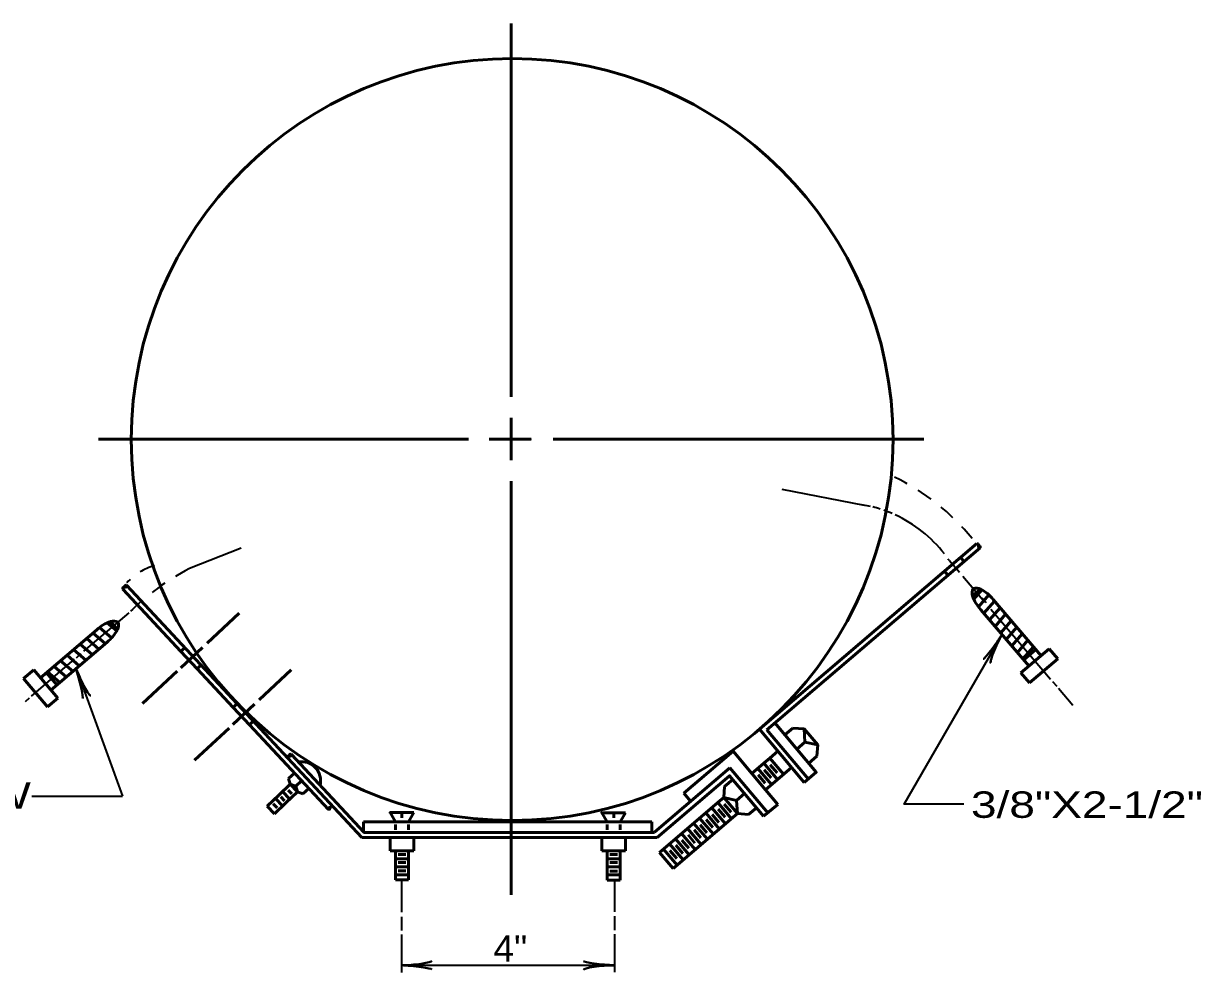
# Model space of a CAD drawing. Extents: x 12366 to 13046, y 9129 to 9570.
# Drawn here: x 12526.1 to 12636.6, y 9238.1 to 9327.8 of the extents above; entities that cross this region are included whole.
import ezdxf

# ---------------------------------------------------------------- set-up
doc = ezdxf.new("R2010")
doc.units = 0
doc.linetypes.add('SHORT_DASHED', pattern=[2.7, 1.5, -1.2])
doc.layers.add('1', color=7, linetype='Continuous', lineweight=53)

msp = doc.modelspace()

# ---------------------------------------------------------------- linework, layer by layer
at = {"layer": '1'}
for p, q in [((12572.209, 9292.546), (12572.209, 9327.828)), ((12572.209, 9288.528), (12572.209, 9290.556)), ((12533.209, 9288.528), (12568.171, 9288.528)), ((12570.139, 9288.528), (12574.118, 9288.528)), ((12572.209, 9286.552), (12572.209, 9288.528)), ((12576.18, 9288.528), (12611.209, 9288.528)), ((12595.683, 9261.128), (12616.214, 9278.663)), ((12596.384, 9261.069), (12616.539, 9278.282)), ((12614.693, 9277.364), (12615.018, 9276.984)), ((12613.172, 9276.065), (12613.497, 9275.685)), ((12558.088, 9250.881), (12535.852, 9274.727)), ((12540.994, 9268.479), (12535.495, 9274.376)), ((12615.827, 9273.727), (12616.583, 9274.372)), ((12615.943, 9273.411), (12616.716, 9274.3)), ((12616.375, 9272.689), (12617.361, 9273.824)), ((12616.611, 9272.423), (12621.156, 9267.102)), ((12616.905, 9272.079), (12617.9, 9273.224)), ((12617.431, 9271.464), (12618.426, 9272.609)), ((12617.76, 9273.388), (12622.296, 9268.077)), ((12534.352, 9271.297), (12534.998, 9270.541)), ((12543.474, 9269.252), (12546.516, 9272.088)), ((12617.956, 9270.849), (12618.951, 9271.994)), ((12618.481, 9270.234), (12619.476, 9271.379)), ((12533.049, 9270.513), (12527.728, 9265.968)), ((12532.705, 9270.219), (12533.85, 9269.224)), ((12533.314, 9270.749), (12534.449, 9269.763)), ((12534.037, 9271.181), (12534.926, 9270.409)), ((12619.006, 9269.619), (12620.002, 9270.764)), ((12534.014, 9269.364), (12528.703, 9264.828)), ((12531.475, 9269.168), (12532.62, 9268.173)), ((12532.09, 9269.694), (12533.235, 9268.699)), ((12619.532, 9269.004), (12620.527, 9270.148)), ((12620.057, 9268.389), (12621.052, 9269.533)), ((12530.245, 9268.118), (12531.389, 9267.123)), ((12530.86, 9268.643), (12532.004, 9267.648)), ((12541.351, 9268.829), (12540.994, 9268.479)), ((12542.529, 9266.833), (12540.994, 9268.479)), ((12540.997, 9266.943), (12543.045, 9268.853)), ((12623.057, 9268.726), (12620.395, 9266.453)), ((12620.583, 9267.774), (12621.578, 9268.918)), ((12621.809, 9268.647), (12620.669, 9267.673)), ((12623.057, 9268.726), (12623.869, 9267.776)), ((12529.015, 9267.067), (12530.159, 9266.072)), ((12529.63, 9267.592), (12530.774, 9266.597)), ((12542.886, 9267.183), (12542.529, 9266.833)), ((12623.869, 9267.776), (12621.207, 9265.503)), ((12527.079, 9266.729), (12526.128, 9265.917)), ((12528.401, 9263.256), (12526.128, 9265.917)), ((12529.352, 9264.067), (12527.079, 9266.729)), ((12529.273, 9265.315), (12528.299, 9266.456)), ((12528.399, 9266.542), (12529.544, 9265.547)), ((12537.373, 9263.564), (12540.633, 9266.604)), ((12545.94, 9263.175), (12542.529, 9266.833)), ((12548.383, 9263.888), (12551.425, 9266.725)), ((12620.395, 9266.453), (12621.207, 9265.503)), ((12529.352, 9264.067), (12528.401, 9263.256)), ((12545.906, 9261.579), (12547.955, 9263.489)), ((12546.297, 9263.525), (12545.94, 9263.175)), ((12547.475, 9261.529), (12545.94, 9263.175)), ((12547.832, 9261.879), (12547.475, 9261.529)), ((12554.932, 9253.533), (12547.475, 9261.529)), ((12542.283, 9258.201), (12545.543, 9261.24)), ((12595.683, 9261.128), (12599.898, 9256.104)), ((12596.384, 9261.069), (12600.281, 9256.426)), ((12598.074, 9260.587), (12598.835, 9261.237)), ((12599.899, 9261.159), (12601.198, 9259.638)), ((12599.222, 9259.244), (12599.971, 9259.906)), ((12551.985, 9258.159), (12551.419, 9258.765)), ((12551.422, 9258.762), (12551.422, 9258.762)), ((12558.276, 9251.413), (12551.454, 9258.728)), ((12588.548, 9255.068), (12593.194, 9259.037)), ((12596.097, 9257.912), (12596.667, 9258.399)), ((12596.667, 9258.399), (12597.427, 9259.049)), ((12596.667, 9258.399), (12597.952, 9256.867)), ((12600.347, 9257.926), (12601.108, 9258.575)), ((12551.723, 9256.986), (12551.17, 9256.479)), ((12585.776, 9251.386), (12592.894, 9257.465)), ((12592.894, 9257.465), (12596.458, 9253.217)), ((12594.956, 9256.938), (12596.096, 9257.912)), ((12595.526, 9257.425), (12596.812, 9255.893)), ((12596.096, 9257.912), (12597.382, 9256.38)), ((12596.136, 9257.288), (12596.786, 9256.528)), ((12596.242, 9255.406), (12598.713, 9257.516)), ((12596.707, 9257.775), (12597.356, 9257.015)), ((12551.326, 9255.92), (12550.238, 9254.887)), ((12551.326, 9255.92), (12552.014, 9255.195)), ((12552.399, 9256.249), (12551.846, 9255.742)), ((12593.15, 9256.381), (12592.378, 9255.722)), ((12595.566, 9256.801), (12596.215, 9256.041)), ((12550.238, 9254.888), (12549.15, 9253.855)), ((12550.785, 9254.359), (12550.441, 9254.722)), ((12551.295, 9254.512), (12550.606, 9255.237)), ((12551.474, 9255.02), (12551.142, 9255.369)), ((12553.074, 9255.512), (12552.521, 9255.005)), ((12588.548, 9255.068), (12589.191, 9254.302)), ((12594.275, 9255.041), (12593.514, 9254.391)), ((12596.242, 9255.406), (12597.408, 9254.015)), ((12549.838, 9253.13), (12549.15, 9253.855)), ((12550.081, 9253.698), (12549.724, 9254.075)), ((12550.617, 9253.869), (12549.929, 9254.594)), ((12591.169, 9253.703), (12592.467, 9252.182)), ((12591.739, 9254.19), (12593.038, 9252.669)), ((12592.309, 9254.677), (12593.608, 9253.156)), ((12592.349, 9254.053), (12592.998, 9253.293)), ((12595.4, 9253.7), (12594.651, 9253.061)), ((12597.408, 9254.015), (12596.074, 9252.896)), ((12561.892, 9253.247), (12561.892, 9252.747)), ((12562.517, 9252.381), (12563.017, 9253.247)), ((12581.902, 9253.237), (12581.902, 9252.737)), ((12582.527, 9252.371), (12583.027, 9253.237)), ((12587.525, 9247.961), (12593.608, 9253.156)), ((12590.028, 9252.729), (12591.327, 9251.208)), ((12590.598, 9253.216), (12591.897, 9251.695)), ((12590.638, 9252.592), (12591.287, 9251.832)), ((12591.208, 9253.079), (12591.857, 9252.319)), ((12591.778, 9253.566), (12592.428, 9252.806)), ((12558.267, 9252.381), (12585.517, 9252.381)), ((12558.267, 9252.381), (12558.267, 9251.381)), ((12561.267, 9252.131), (12561.267, 9251.631)), ((12562.517, 9252.131), (12562.517, 9251.631)), ((12581.277, 9252.121), (12581.277, 9251.621)), ((12582.527, 9252.121), (12582.527, 9251.621)), ((12585.517, 9252.381), (12585.517, 9251.381)), ((12588.887, 9251.755), (12590.186, 9250.234)), ((12589.458, 9252.242), (12590.756, 9250.721)), ((12589.497, 9251.618), (12590.146, 9250.858)), ((12590.067, 9252.105), (12590.717, 9251.345)), ((12558.088, 9250.881), (12586.017, 9250.881)), ((12558.267, 9251.381), (12585.767, 9251.381)), ((12560.767, 9250.881), (12560.767, 9249.631)), ((12563.017, 9250.881), (12563.017, 9249.631)), ((12580.777, 9250.871), (12580.777, 9249.621)), ((12583.027, 9250.871), (12583.027, 9249.621)), ((12587.747, 9250.781), (12589.046, 9249.26)), ((12588.317, 9251.268), (12589.616, 9249.747)), ((12588.357, 9250.644), (12589.006, 9249.884)), ((12588.927, 9251.131), (12589.576, 9250.371)), ((12560.767, 9249.631), (12563.017, 9249.631)), ((12561.267, 9249.631), (12561.267, 9246.881)), ((12561.517, 9249.283), (12562.267, 9249.283)), ((12562.517, 9249.631), (12562.517, 9246.881)), ((12580.777, 9249.621), (12583.027, 9249.621)), ((12581.277, 9249.621), (12581.277, 9246.871)), ((12581.527, 9249.273), (12582.277, 9249.273)), ((12582.527, 9249.621), (12582.527, 9246.871)), ((12586.226, 9249.482), (12587.525, 9247.961)), ((12586.606, 9249.806), (12587.905, 9248.286)), ((12586.606, 9249.806), (12587.905, 9248.286)), ((12587.176, 9250.293), (12588.475, 9248.773)), ((12587.216, 9249.67), (12587.865, 9248.91)), ((12587.786, 9250.157), (12588.435, 9249.397)), ((12561.267, 9248.891), (12562.517, 9248.891)), ((12561.267, 9248.128), (12562.517, 9248.128)), ((12561.517, 9248.541), (12562.267, 9248.541)), ((12581.277, 9248.881), (12582.527, 9248.881)), ((12581.277, 9248.118), (12582.527, 9248.118)), ((12581.527, 9248.53), (12582.277, 9248.53)), ((12561.267, 9247.381), (12562.517, 9247.381)), ((12561.517, 9247.736), (12562.267, 9247.736)), ((12581.277, 9247.371), (12582.527, 9247.371)), ((12581.527, 9247.726), (12582.277, 9247.726)), ((12561.267, 9246.881), (12562.517, 9246.881)), ((12581.277, 9246.871), (12582.527, 9246.871))]:
    msp.add_line(p, q, dxfattribs=at)
at = {"layer": '1', "lineweight": 13}
for p, q in [((12574.118, 9288.528), (12574.149, 9288.528)), ((12546.708, 9262.352), (12547.061, 9262.681))]:
    msp.add_line(p, q, dxfattribs=at)
at = {"layer": '1', "lineweight": 35}
for p, q in [((12597.786, 9283.827), (12605.576, 9282.313)), ((12605.33, 9282.361), (12606.13, 9282.206)), ((12546.685, 9278.231), (12541.8, 9276.307)), ((12613.608, 9277.095), (12614.582, 9275.954)), ((12614.904, 9275.578), (12616.985, 9273.141)), ((12616.697, 9273.558), (12617.099, 9273.104)), ((12617.563, 9272.464), (12623.2, 9265.863)), ((12531.833, 9268.487), (12536.092, 9272.125)), ((12531.12, 9267.879), (12531.575, 9268.267)), ((12526.878, 9264.256), (12530.953, 9267.737)), ((12531.087, 9266.872), (12535.483, 9254.794)), ((12623.39, 9265.641), (12623.784, 9265.18)), ((12623.94, 9264.997), (12625.298, 9263.407)), ((12526.299, 9263.761), (12526.685, 9264.091)), ((12526.89, 9254.794), (12535.483, 9254.794)), ((12561.852, 9246.876), (12561.852, 9243.823)), ((12581.986, 9246.917), (12581.986, 9243.864)), ((12561.852, 9243.41), (12561.852, 9242.09)), ((12581.986, 9243.451), (12581.986, 9242.131)), ((12561.852, 9241.718), (12561.852, 9238.126)), ((12581.986, 9241.76), (12581.986, 9238.167)), ((12561.839, 9238.819), (12581.926, 9238.819))]:
    msp.add_line(p, q, dxfattribs=at)
at = {"layer": '1'}
for points in [[(12572.209, 9245.479), (12572.209, 9252.605), (12572.209, 9284.563)], [(12597.145, 9261.719), (12601.047, 9257.068), (12599.898, 9256.104)], [(12598.835, 9261.237), (12599.899, 9261.159), (12599.971, 9259.906), (12601.198, 9259.638), (12601.108, 9258.575)], [(12593.194, 9259.037), (12594.956, 9256.938), (12596.242, 9255.406)], [(12551.17, 9256.479), (12551.326, 9255.92), (12551.846, 9255.742), (12552.014, 9255.195), (12552.521, 9255.005)], [(12586.017, 9250.881), (12592.86, 9256.726), (12596.074, 9252.896)], [(12552.014, 9255.195), (12550.926, 9254.162), (12549.838, 9253.13)], [(12592.378, 9255.722), (12592.309, 9254.677), (12593.514, 9254.391), (12593.608, 9253.156), (12594.651, 9253.061)], [(12586.226, 9249.482), (12591.739, 9254.19), (12592.309, 9254.677)], [(12561.267, 9252.381), (12560.767, 9253.247), (12563.017, 9253.247)], [(12581.277, 9252.371), (12580.777, 9253.237), (12583.027, 9253.237)]]:
    msp.add_lwpolyline(points, dxfattribs=at)
at = {"layer": '1', "lineweight": 35}
msp.add_lwpolyline([(12614.99, 9254.045), (12609.359, 9254.045), (12618.615, 9270.077)], dxfattribs=at)
at = {"layer": '1'}
msp.add_circle((12572.305, 9288.504), 36, dxfattribs=at)
at = {"layer": '1', "linetype": 'SHORT_DASHED', "lineweight": 35}
for centre, radius, start, end in [((12599.1, 9265.567), 21.518, 39.09076, 64.25674), ((12540.298, 9270.839), 6.039, 107.18277, 136.93055), ((12552.417, 9255.827), 23.068, 117.40174, 135.04708)]:
    msp.add_arc(centre, radius, start, end, dxfattribs=at)
at = {"layer": '1', "lineweight": 35}
for start, end in [(72.09704, 75.39826), (66.7088, 70.55356), (37.97532, 65.20978), (34.61481, 35.37094)]:
    msp.add_arc((12603.224, 9269.927), 12.618, start, end, dxfattribs=at)
at = {"layer": '1'}
for centre, radius, start, end in [((12616.238, 9278.519), 0.146, 341.35274, 99.6479), ((12616.514, 9278.426), 0.146, 161.35274, 279.6479), ((12616.401, 9278.329), 0.146, 341.35274, 99.6479), ((12535.815, 9274.586), 0.146, 75.35274, 193.6479), ((12535.71, 9274.692), 0.146, 255.35274, 13.6479), ((12535.636, 9274.41), 0.146, 75.35274, 193.6479), ((12616.776, 9273.996), 0.986, 154.26025, 195.83671), ((12618.852, 9274.659), 3.165, 197.13743, 224.94055), ((12616.168, 9273.478), 0.986, 64.26025, 105.83671), ((12614.917, 9271.186), 3.596, 37.7559, 62.16939), ((12535.285, 9268.273), 3.165, 107.13743, 134.94055), ((12534.622, 9270.348), 0.986, 64.26025, 105.83671), ((12531.812, 9272.207), 3.596, 307.7559, 332.16939), ((12534.103, 9270.957), 0.986, 334.26025, 15.83671), ((12551.196, 9258.454), 0.146, 73.35274, 191.6479), ((12551.381, 9258.623), 0.146, 73.35274, 191.6479), ((12551.28, 9258.733), 0.146, 253.35274, 11.6479), ((12551.28, 9258.733), 0.146, 11.56977, 11.63706), ((12552.409, 9256.27), 1.791, 346.12036, 99.8792), ((12555.064, 9253.593), 0.146, 86.35274, 204.6479), ((12554.941, 9253.678), 0.146, 266.35274, 24.6479), ((12555.083, 9253.884), 0.146, 266.35274, 24.6479)]:
    msp.add_arc(centre, radius, start, end, dxfattribs=at)
at = {"layer": '1', "lineweight": 40}
for centre, major_axis, ratio, start_param, end_param in [((12617.872, 9269.212), (-1.03, -1.433), 0.07063, 6.2823074, 8.5597026), ((12618.309, 9268.994), (0.758, 1.625), 0.122415, 0.8963533, 3.1415927), ((12531.271, 9265.746), (0.436, -1.711), 0.07063, 6.2823074, 8.5597026), ((12531.72, 9265.941), (-0.757, 1.625), 0.122415, 0.8963533, 3.1415927), ((12562.93, 9239.095), (-1.786, -0.156), 0.122415, 0.8963533, 3.1415927), ((12562.959, 9238.608), (1.756, -0.176), 0.07063, 6.2823074, 8.5597026), ((12580.835, 9238.543), (1.786, 0.156), 0.122415, 0.8963533, 3.1415927), ((12580.805, 9239.031), (1.756, -0.176), 0.07063, 3.1407148, 5.41811)]:
    msp.add_ellipse(centre, major_axis=major_axis, ratio=ratio, start_param=start_param, end_param=end_param, dxfattribs=at)

# ---------------------------------------------------------------- texts
at = {"layer": '1'}
for s, width, p in [('3/8"X2-1/2" LAG SCREW', 1.3, (12477.593, 9253.608)), ('3/8"X2-1/2" LAG SCREW', 1.3, (12615.676, 9252.751)), ('4"', 1.05, (12570.533, 9239.154))]:
    msp.add_text(s, height=2.5, dxfattribs=dict(at, width=width)).set_placement(p)

doc.saveas('drawing.dxf')
